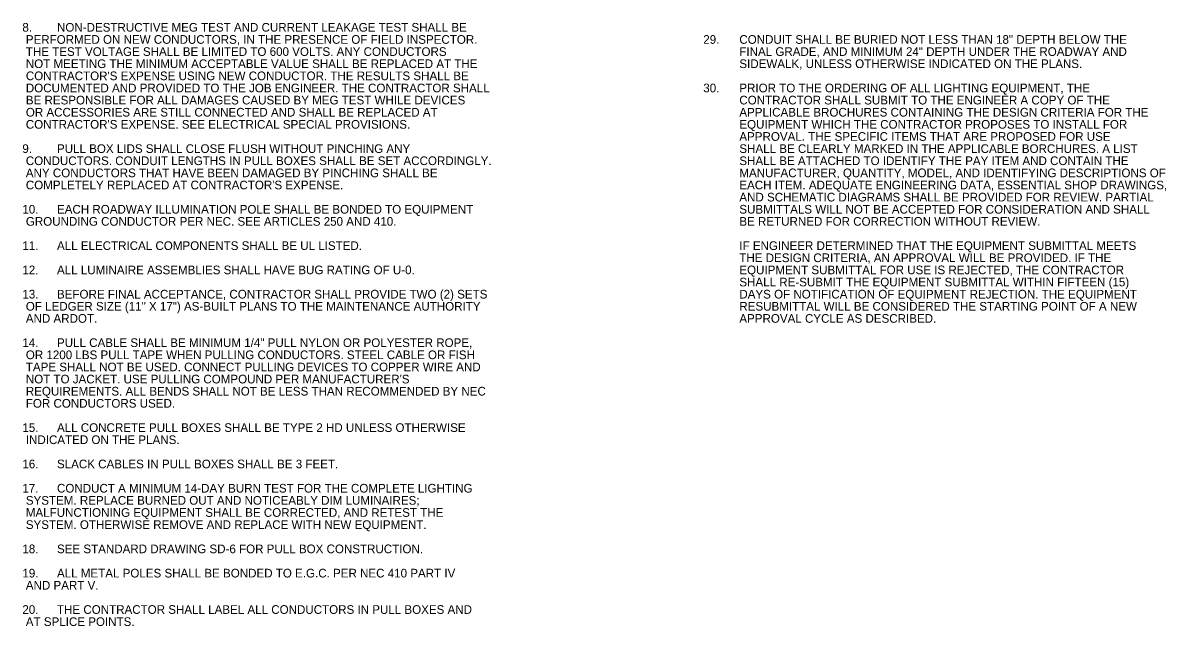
# Model space of a CAD drawing. Extents: x 478 to 2985, y 29 to 1032.
# Drawn here: x 2160 to 2985, y 35 to 470 of the extents above; entities that cross this region are included whole.
import ezdxf

# ---------------------------------------------------------------- set-up
doc = ezdxf.new("R2010")
doc.units = 0
doc.layers.add('E-ANNO-NOTE', color=7, linetype='Continuous')

msp = doc.modelspace()

# ---------------------------------------------------------------- texts
at = {"layer": 'E-ANNO-NOTE'}
for s, p in [('8.', (2159.72, 464.01)), ('NON-DESTRUCTIVE MEG TEST AND CURRENT LEAKAGE TEST SHALL BE ', (2184.72, 464.01)), ('PERFORMED ON NEW CONDUCTORS, IN THE PRESENCE OF FIELD INSPECTOR. ', (2162.22, 455.26)), ('29.', (2651.22, 455.26)), ('CONDUIT SHALL BE BURIED NOT LESS THAN 18" DEPTH BELOW THE ', (2677.26, 455.26)), ('THE TEST VOLTAGE SHALL BE LIMITED TO 600 VOLTS. ANY CONDUCTORS ', (2162.22, 446.51)), ('FINAL GRADE, AND MINIMUM 24" DEPTH UNDER THE ROADWAY AND ', (2677.26, 446.51)), ('NOT MEETING THE MINIMUM ACCEPTABLE VALUE SHALL BE REPLACED AT THE ', (2162.22, 437.76)), ('SIDEWALK, UNLESS OTHERWISE INDICATED ON THE PLANS.', (2677.26, 437.76)), ("CONTRACTOR'S EXPENSE USING NEW CONDUCTOR. THE RESULTS SHALL BE ", (2162.22, 429.01)), ('DOCUMENTED AND PROVIDED TO THE JOB ENGINEER. THE CONTRACTOR SHALL ', (2162.22, 420.26)), ('30.', (2651.22, 420.26)), ('PRIOR TO THE ORDERING OF ALL LIGHTING EQUIPMENT, THE ', (2677.26, 420.26)), ('BE RESPONSIBLE FOR ALL DAMAGES CAUSED BY MEG TEST WHILE DEVICES ', (2162.22, 411.51)), ('CONTRACTOR SHALL SUBMIT TO THE ENGINEER A COPY OF THE ', (2677.26, 411.51)), ('OR ACCESSORIES ARE STILL CONNECTED AND SHALL BE REPLACED AT ', (2162.22, 402.76)), ('APPLICABLE BROCHURES CONTAINING THE DESIGN CRITERIA FOR THE ', (2677.26, 402.76)), ("CONTRACTOR'S EXPENSE. SEE ELECTRICAL SPECIAL PROVISIONS.", (2162.22, 394.01)), ('EQUIPMENT WHICH THE CONTRACTOR PROPOSES TO INSTALL FOR ', (2677.26, 394.01)), ('APPROVAL. THE SPECIFIC ITEMS THAT ARE PROPOSED FOR USE ', (2677.26, 385.26)), ('9.', (2159.72, 376.51)), ('PULL BOX LIDS SHALL CLOSE FLUSH WITHOUT PINCHING ANY ', (2184.72, 376.51)), ('SHALL BE CLEARLY MARKED IN THE APPLICABLE BORCHURES. A LIST ', (2677.26, 376.51)), ('CONDUCTORS. CONDUIT LENGTHS IN PULL BOXES SHALL BE SET ACCORDINGLY. ', (2162.22, 367.76)), ('SHALL BE ATTACHED TO IDENTIFY THE PAY ITEM AND CONTAIN THE ', (2677.26, 367.76)), ('ANY CONDUCTORS THAT HAVE BEEN DAMAGED BY PINCHING SHALL BE ', (2162.22, 359.01)), ('MANUFACTURER, QUANTITY, MODEL, AND IDENTIFYING DESCRIPTIONS OF ', (2677.26, 359.01)), ("COMPLETELY REPLACED AT CONTRACTOR'S EXPENSE.", (2162.22, 350.26)), ('EACH ITEM. ADEQUATE ENGINEERING DATA, ESSENTIAL SHOP DRAWINGS, ', (2677.26, 350.26)), ('AND SCHEMATIC DIAGRAMS SHALL BE PROVIDED FOR REVIEW. PARTIAL ', (2677.26, 341.51)), ('10.', (2159.72, 332.76)), ('EACH ROADWAY ILLUMINATION POLE SHALL BE BONDED TO EQUIPMENT ', (2184.72, 332.76)), ('SUBMITTALS WILL NOT BE ACCEPTED FOR CONSIDERATION AND SHALL ', (2677.26, 332.76)), ('GROUNDING CONDUCTOR PER NEC. SEE ARTICLES 250 AND 410.', (2162.22, 324.01)), ('BE RETURNED FOR CORRECTION WITHOUT REVIEW.', (2677.26, 324.01)), ('11.', (2159.72, 306.51)), ('ALL ELECTRICAL COMPONENTS SHALL BE UL LISTED.', (2184.72, 306.51)), ('IF ENGINEER DETERMINED THAT THE EQUIPMENT SUBMITTAL MEETS ', (2677.26, 306.51)), ('THE DESIGN CRITERIA, AN APPROVAL WILL BE PROVIDED. IF THE ', (2677.26, 297.76)), ('12.', (2159.72, 289.01)), ('ALL LUMINAIRE ASSEMBLIES SHALL HAVE BUG RATING OF U-0.', (2184.72, 289.01)), ('EQUIPMENT SUBMITTAL FOR USE IS REJECTED, THE CONTRACTOR ', (2677.26, 289.01)), ('SHALL RE-SUBMIT THE EQUIPMENT SUBMITTAL WITHIN FIFTEEN (15) ', (2677.26, 280.26)), ('13.', (2159.72, 271.51)), ('BEFORE FINAL ACCEPTANCE, CONTRACTOR SHALL PROVIDE TWO (2) SETS ', (2184.72, 271.51)), ('DAYS OF NOTIFICATION OF EQUIPMENT REJECTION. THE EQUIPMENT ', (2677.26, 271.51)), ('OF LEDGER SIZE (11" X 17") AS-BUILT PLANS TO THE MAINTENANCE AUTHORITY ', (2162.22, 262.76)), ('RESUBMITTAL WILL BE CONSIDERED THE STARTING POINT OF A NEW ', (2677.26, 262.76)), ('AND ARDOT.', (2162.22, 254.01)), ('APPROVAL CYCLE AS DESCRIBED.', (2677.26, 254.01)), ('14.', (2159.72, 236.51)), ('PULL CABLE SHALL BE MINIMUM 1/4" PULL NYLON OR POLYESTER ROPE, ', (2184.72, 236.51)), ('OR 1200 LBS PULL TAPE WHEN PULLING CONDUCTORS. STEEL CABLE OR FISH ', (2162.22, 227.76)), ('TAPE SHALL NOT BE USED. CONNECT PULLING DEVICES TO COPPER WIRE AND ', (2162.22, 219.01)), ("NOT TO JACKET. USE PULLING COMPOUND PER MANUFACTURER'S ", (2162.22, 210.26)), ('REQUIREMENTS. ALL BENDS SHALL NOT BE LESS THAN RECOMMENDED BY NEC ', (2162.22, 201.51)), ('FOR CONDUCTORS USED.', (2162.22, 192.76)), ('ALL CONCRETE PULL BOXES SHALL BE TYPE 2 HD UNLESS OTHERWISE ', (2184.72, 175.26)), ('15.', (2159.72, 175.26)), ('INDICATED ON THE PLANS.', (2162.22, 166.51)), ('16.', (2159.72, 149.01)), ('SLACK CABLES IN PULL BOXES SHALL BE 3 FEET.', (2184.72, 149.01)), ('17.', (2159.72, 131.51)), ('CONDUCT A MINIMUM 14-DAY BURN TEST FOR THE COMPLETE LIGHTING ', (2184.72, 131.51)), ('SYSTEM. REPLACE BURNED OUT AND NOTICEABLY DIM LUMINAIRES; ', (2162.22, 122.76)), ('MALFUNCTIONING EQUIPMENT SHALL BE CORRECTED, AND RETEST THE ', (2162.22, 114.01)), ('SYSTEM. OTHERWISE REMOVE AND REPLACE WITH NEW EQUIPMENT.', (2162.22, 105.26)), ('18.', (2159.72, 87.76)), ('SEE STANDARD DRAWING SD-6 FOR PULL BOX CONSTRUCTION.', (2184.72, 87.76)), ('19.', (2159.72, 70.26)), ('ALL METAL POLES SHALL BE BONDED TO E.G.C. PER NEC 410 PART IV ', (2184.72, 70.26)), ('AND PART V.', (2162.22, 61.51)), ('20.', (2159.72, 44.01)), ('THE CONTRACTOR SHALL LABEL ALL CONDUCTORS IN PULL BOXES AND ', (2184.72, 44.01)), ('AT SPLICE POINTS.', (2162.22, 35.26))]:
    msp.add_text(s, height=6.25, rotation=360, dxfattribs=at).set_placement(p)

doc.saveas('drawing.dxf')
